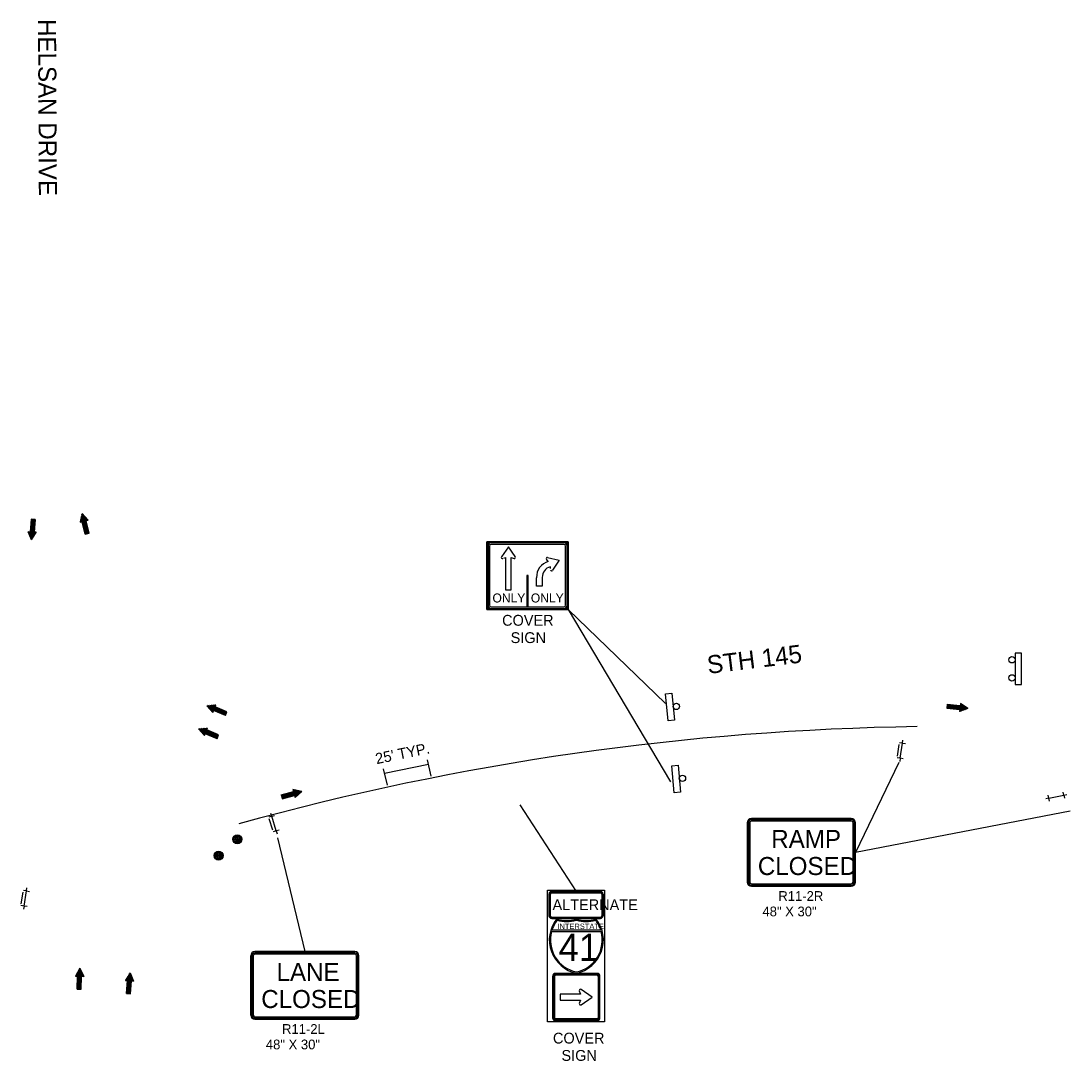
# Model space of a CAD drawing. Extents: x 358662 to 361839, y 132407 to 133741.
# Drawn here: x 360554 to 361135, y 133165 to 133741 of the extents above; entities that cross this region are included whole.
import ezdxf

# ---------------------------------------------------------------- set-up
doc = ezdxf.new("R2010")
doc.units = 0
for name, color, linetype in [('E_BLD_Dash', 7, 'Continuous'), ('E_BLD_Footing', 7, 'Continuous'), ('E_DTM_RandomShots', 7, 'Continuous'), ('E_MISCPROP_ShtDash', 7, 'Continuous'), ('E_WTR_Wetland', 7, 'Continuous'), ('P_FTMS_LaneLbl', 7, 'Continuous')]:
    doc.layers.add(name, color=color, linetype=linetype)

msp = doc.modelspace()

# ---------------------------------------------------------------- linework, layer by layer
at = {"layer": 'E_BLD_Dash'}
for p, q in [((361042.31, 133340.9), (361040.63, 133341.15)), ((361041.06, 133332.5), (361042.31, 133340.9)), ((361042.31, 133340.9), (361042.56, 133342.59)), ((361042.31, 133340.9), (361043.99, 133340.66)), ((361039.53, 133333.73), (361040.48, 133340.16)), ((361041.06, 133332.5), (361039.38, 133332.74)), ((361041.06, 133332.5), (361040.81, 133330.81)), ((361042.74, 133332.25), (361041.06, 133332.5)), ((361123.45, 133310.36), (361123.09, 133312.03)), ((361123.45, 133310.36), (361131.76, 133312.16)), ((361131.76, 133312.16), (361131.4, 133313.82)), ((361131.76, 133312.16), (361133.42, 133312.52)), ((361131.76, 133312.16), (361132.12, 133310.5)), ((361123.45, 133310.36), (361121.79, 133310.01)), ((361123.81, 133308.7), (361123.45, 133310.36)), ((360692.71, 133300.36), (360691.08, 133299.86)), ((360692.71, 133300.36), (360692.22, 133301.98)), ((360692.71, 133300.36), (360694.34, 133300.85)), ((360695.18, 133292.22), (360692.71, 133300.36)), ((360693.26, 133292.69), (360691.38, 133298.91)), ((360695.18, 133292.22), (360693.55, 133291.73)), ((360696.8, 133292.72), (360695.18, 133292.22)), ((360695.18, 133292.22), (360695.67, 133290.6)), ((360556.76, 133258.99), (360557.03, 133260.67)), ((360553.9, 133251.85), (360554.93, 133258.27)), ((360556.76, 133258.99), (360555.08, 133259.26)), ((360555.42, 133250.59), (360556.76, 133258.99)), ((360556.76, 133258.99), (360558.44, 133258.72)), ((360555.42, 133250.59), (360553.75, 133250.86)), ((360555.42, 133250.59), (360555.16, 133248.92)), ((360557.1, 133250.33), (360555.42, 133250.59))]:
    msp.add_line(p, q, dxfattribs=at)
for centre, radius in [((360673.65, 133287.65), 2.5), ((360673.65, 133287.65), 2), ((360673.65, 133287.65), 1.5), ((360673.65, 133287.65), 1), ((360673.65, 133287.65), 0.5), ((360673.65, 133287.65), 0.25), ((360663.24, 133278.55), 2.5), ((360663.24, 133278.55), 2), ((360663.24, 133278.55), 1.5), ((360663.24, 133278.55), 1), ((360663.24, 133278.55), 0.5), ((360663.24, 133278.55), 0.25)]:
    msp.add_circle(centre, radius, dxfattribs=at)
at = {"layer": 'E_BLD_Footing'}
for p, q in [((360559.31, 133465.13), (360558.79, 133458.03)), ((360559.76, 133465.1), (360559.01, 133454.97)), ((360561.56, 133464.96), (360559.31, 133465.13)), ((360560.21, 133465.06), (360559.4, 133454.07)), ((360560.66, 133465.03), (360559.84, 133453.92)), ((360561.11, 133465), (360560.35, 133454.78)), ((360560.43, 133465.05), (360560.43, 133465.05)), ((360561.56, 133464.96), (360561.03, 133457.86)), ((360587.58, 133468.18), (360586.54, 133463.38)), ((360586.54, 133463.38), (360590.9, 133464.5)), ((360586.75, 133463.45), (360586.65, 133463.86)), ((360587.19, 133463.57), (360586.86, 133464.84)), ((360587.62, 133463.68), (360587.07, 133465.82)), ((360589.85, 133456.87), (360587.28, 133466.79)), ((360590.28, 133456.98), (360587.49, 133467.77)), ((360587.58, 133468.18), (360590.9, 133464.5)), ((360589.41, 133456.76), (360587.63, 133463.65)), ((360590.72, 133457.1), (360587.96, 133467.77)), ((360591.16, 133457.21), (360588.61, 133467.04)), ((360589.8, 133464.24), (360589.26, 133466.32)), ((360591.59, 133457.32), (360589.81, 133464.22)), ((360590.24, 133464.36), (360589.92, 133465.59)), ((360590.67, 133464.47), (360590.57, 133464.87)), ((360562.15, 133457.77), (360557.67, 133458.11)), ((360559.62, 133453.56), (360557.67, 133458.11)), ((360557.89, 133458.07), (360557.86, 133457.66)), ((360558.34, 133458.03), (360558.24, 133456.76)), ((360558.79, 133458), (360558.63, 133455.86)), ((360559.62, 133453.56), (360562.15, 133457.77)), ((360561.03, 133457.83), (360560.87, 133455.63)), ((360561.48, 133457.8), (360561.38, 133456.49)), ((360561.93, 133457.77), (360561.9, 133457.35)), ((360589.41, 133456.76), (360591.59, 133457.32)), ((360590.5, 133457.04), (360590.5, 133457.04)), ((360656.83, 133361.66), (360661.76, 133362.08)), ((360656.83, 133361.66), (360660.03, 133357.93)), ((360667.39, 133357.05), (360657.11, 133361.34)), ((360667.56, 133357.47), (360657.39, 133361.71)), ((360667.21, 133356.63), (360657.76, 133360.58)), ((360667.73, 133357.88), (360658.36, 133361.79)), ((360660.44, 133358.97), (360658.41, 133359.82)), ((360660.27, 133358.56), (360659.06, 133359.06)), ((360661.31, 133361.05), (360659.33, 133361.87)), ((360660.1, 133358.14), (360659.71, 133358.3)), ((360660.03, 133357.93), (360661.76, 133362.08)), ((360661.48, 133361.46), (360660.31, 133361.96)), ((360667.04, 133356.22), (360660.47, 133358.96)), ((360661.66, 133361.88), (360661.28, 133362.04)), ((360667.91, 133358.3), (360661.33, 133361.04)), ((360667.04, 133356.22), (360667.91, 133358.3)), ((361067.18, 133362.55), (361066.92, 133360.31)), ((361066.92, 133360.31), (361074, 133359.5)), ((361066.97, 133360.76), (361077.06, 133359.6)), ((361067.03, 133361.21), (361077.97, 133359.94)), ((361067.05, 133361.43), (361067.05, 133361.43)), ((361067.08, 133361.65), (361078.14, 133360.38)), ((361067.13, 133362.1), (361077.31, 133360.93)), ((361067.18, 133362.55), (361074.25, 133361.73)), ((361074.39, 133362.85), (361073.87, 133358.38)), ((361078.5, 133360.14), (361073.87, 133358.38)), ((361073.92, 133358.6), (361074.33, 133358.55)), ((361073.97, 133359.05), (361075.24, 133358.9)), ((361074.02, 133359.49), (361076.15, 133359.25)), ((361074.28, 133361.73), (361076.47, 133361.48)), ((361074.33, 133362.18), (361075.64, 133362.03)), ((361074.38, 133362.62), (361074.8, 133362.57)), ((361078.5, 133360.14), (361074.39, 133362.85)), ((360667.47, 133357.26), (360667.47, 133357.26)), ((360652.21, 133348.82), (360657.14, 133349.24)), ((360652.21, 133348.82), (360655.41, 133345.09)), ((360662.76, 133344.21), (360652.48, 133348.5)), ((360662.94, 133344.63), (360652.77, 133348.87)), ((360662.59, 133343.8), (360653.13, 133347.74)), ((360663.11, 133345.04), (360653.74, 133348.95)), ((360655.82, 133346.13), (360653.78, 133346.98)), ((360656.69, 133348.21), (360654.71, 133349.04)), ((360655.41, 133345.09), (360657.14, 133349.24)), ((360656.86, 133348.63), (360655.68, 133349.12)), ((360657.03, 133349.04), (360656.65, 133349.2)), ((360663.28, 133345.46), (360656.71, 133348.2)), ((360655.65, 133345.72), (360654.43, 133346.22)), ((360655.47, 133345.3), (360655.08, 133345.47)), ((360662.42, 133343.38), (360655.84, 133346.12)), ((360662.42, 133343.38), (360663.28, 133345.46)), ((360662.85, 133344.42), (360662.85, 133344.42)), ((360697.92, 133312.25), (360704.8, 133314.1)), ((360697.92, 133312.25), (360698.51, 133310.08)), ((360698.04, 133311.82), (360707.93, 133314.48)), ((360698.16, 133311.38), (360708.91, 133314.28)), ((360698.27, 133310.95), (360708.91, 133313.81)), ((360698.39, 133310.51), (360708.19, 133313.15)), ((360698.51, 133310.08), (360705.38, 133311.93)), ((360709.33, 133314.19), (360704.51, 133315.19)), ((360704.51, 133315.19), (360705.68, 133310.84)), ((360704.59, 133314.98), (360705, 133315.09)), ((360704.71, 133314.54), (360705.98, 133314.89)), ((360704.82, 133314.11), (360706.96, 133314.68)), ((360705.41, 133311.94), (360707.48, 133312.49)), ((360705.53, 133311.5), (360706.76, 133311.83)), ((360709.33, 133314.19), (360705.68, 133310.84)), ((360698.21, 133311.17), (360698.21, 133311.17)), ((360705.64, 133311.07), (360706.04, 133311.17)), ((360586.41, 133216.1), (360584, 133211.81)), ((360584.68, 133211.8), (360584.74, 133213.11)), ((360585.13, 133211.78), (360585.23, 133213.98)), ((360585.25, 133204.62), (360585.72, 133214.86)), ((360585.7, 133204.6), (360586.21, 133215.73)), ((360586.15, 133204.58), (360586.65, 133215.59)), ((360586.41, 133216.1), (360588.5, 133211.6)), ((360586.6, 133204.56), (360587.06, 133214.7)), ((360587.37, 133211.68), (360587.47, 133213.82)), ((360587.82, 133211.66), (360587.88, 133212.93)), ((360614.19, 133213.62), (360611.65, 133209.4)), ((360613.14, 133202.15), (360613.97, 133213.25)), ((360613.59, 133202.11), (360614.41, 133213.1)), ((360614.19, 133213.62), (360616.14, 133209.07)), ((360584, 133211.81), (360588.5, 133211.6)), ((360584.23, 133211.82), (360584.25, 133212.24)), ((360584.8, 133204.64), (360585.13, 133211.75)), ((360587.05, 133204.54), (360587.37, 133211.65)), ((360588.27, 133211.64), (360588.29, 133212.05)), ((360611.65, 133209.4), (360616.14, 133209.07)), ((360611.88, 133209.41), (360611.91, 133209.83)), ((360612.24, 133202.21), (360612.78, 133209.31)), ((360612.33, 133209.38), (360612.43, 133210.69)), ((360612.69, 133202.18), (360613.46, 133212.4)), ((360612.78, 133209.34), (360612.94, 133211.54)), ((360614.04, 133202.08), (360614.8, 133212.2)), ((360614.49, 133202.05), (360615.02, 133209.15)), ((360615.02, 133209.17), (360615.18, 133211.31)), ((360615.47, 133209.14), (360615.57, 133210.41)), ((360615.92, 133209.11), (360615.95, 133209.52)), ((360584.8, 133204.64), (360587.05, 133204.54)), ((360585.93, 133204.59), (360585.93, 133204.59)), ((360612.24, 133202.21), (360614.49, 133202.05)), ((360613.37, 133202.13), (360613.37, 133202.13))]:
    msp.add_line(p, q, dxfattribs=at)
at = {"layer": 'E_DTM_RandomShots'}
msp.add_arc((361071.64, 131864.2), 1486, 90.81641, 105.50174, dxfattribs=at)
at = {"layer": 'E_MISCPROP_ShtDash'}
for p, q in [((360956.29, 133296.73), (360956.29, 133263.9)), ((360956.92, 133296.73), (360956.92, 133263.9)), ((360957.7, 133296.71), (360957.7, 133263.9)), ((361013.97, 133299.07), (360958.64, 133299.07)), ((361013.97, 133298.45), (360958.64, 133298.45)), ((361013.97, 133297.66), (360958.64, 133297.66)), ((361014.91, 133263.9), (361014.91, 133296.73)), ((361015.69, 133263.9), (361015.69, 133296.73)), ((361016.31, 133263.9), (361016.31, 133296.73)), ((360958.64, 133262.96), (361013.97, 133262.96)), ((360958.64, 133262.18), (361013.97, 133262.18)), ((360958.64, 133261.56), (361013.97, 133261.56)), ((360738.73, 133225.35), (360683.4, 133225.35)), ((360738.73, 133224.73), (360683.4, 133224.73)), ((360681.05, 133223.01), (360681.05, 133190.19)), ((360681.68, 133223.01), (360681.68, 133190.19)), ((360682.46, 133222.99), (360682.46, 133190.19)), ((360738.73, 133223.95), (360683.4, 133223.95)), ((360739.67, 133190.19), (360739.67, 133223.01)), ((360740.45, 133190.19), (360740.45, 133223.01)), ((360741.07, 133190.19), (360741.07, 133223.01)), ((360683.4, 133189.25), (360738.73, 133189.25)), ((360683.4, 133188.47), (360738.73, 133188.47)), ((360683.4, 133187.84), (360738.73, 133187.84))]:
    msp.add_line(p, q, dxfattribs=at)
for centre, radius, start, end in [((360958.64, 133296.73), 2.34, 90, 180), ((360958.64, 133296.73), 1.72, 90, 180), ((360958.64, 133296.73), 0.938, 90, 181.0779), ((361013.97, 133296.73), 2.34, 0, 90), ((361013.97, 133296.73), 1.72, 0, 90), ((361013.97, 133296.73), 0.938, 0, 90), ((360958.64, 133263.9), 2.34, 180, 270), ((360958.64, 133263.9), 1.72, 180, 270), ((360958.64, 133263.9), 0.938, 180, 270), ((361013.97, 133263.9), 0.938, 270, 360), ((361013.97, 133263.9), 1.72, 270, 360), ((361013.97, 133263.9), 2.34, 270, 360), ((360683.4, 133223.01), 2.34, 90, 180), ((360683.4, 133223.01), 1.72, 90, 180), ((360738.73, 133223.01), 2.34, 0, 90), ((360738.73, 133223.01), 1.72, 0, 90), ((360683.4, 133223.01), 0.938, 90, 181.0779), ((360738.73, 133223.01), 0.938, 0, 90), ((360683.4, 133190.19), 2.34, 180, 270), ((360683.4, 133190.19), 1.72, 180, 270), ((360683.4, 133190.19), 0.938, 180, 270), ((360738.73, 133190.19), 0.938, 270, 360), ((360738.73, 133190.19), 1.72, 270, 360), ((360738.73, 133190.19), 2.34, 270, 360)]:
    msp.add_arc(centre, radius, start, end, dxfattribs=at)
at = {"layer": 'E_WTR_Wetland'}
for p, q in [((360812.01, 133452.48), (360812.01, 133449.65)), ((360857.01, 133452.48), (360812.01, 133452.48)), ((360854.67, 133451.86), (360814.36, 133451.86)), ((360857.01, 133414.98), (360857.01, 133452.48)), ((360812.01, 133449.65), (360812.01, 133414.98)), ((360813.42, 133450.14), (360813.42, 133417.33)), ((360854.67, 133451.08), (360814.36, 133451.08)), ((360823.91, 133449.72), (360820.08, 133444.25)), ((360827.71, 133444.29), (360823.91, 133449.72)), ((360855.61, 133417.33), (360855.61, 133450.14)), ((360821.44, 133443.5), (360822.35, 133443.78)), ((360822.35, 133443.78), (360822.35, 133439.41)), ((360825.48, 133440.06), (360825.48, 133443.78)), ((360825.48, 133443.78), (360827.02, 133443.33)), ((360825.48, 133425.82), (360825.48, 133440.06)), ((360846.01, 133441.51), (360844.98, 133442.82)), ((360845.61, 133443.82), (360852.06, 133442.33)), ((360852.06, 133442.33), (360848.43, 133436.73)), ((360822.35, 133439.48), (360822.35, 133425.82)), ((360847.23, 133437.7), (360847.15, 133438.57)), ((360839.56, 133427.92), (360839.56, 133432.61)), ((360842.69, 133427.92), (360839.56, 133427.92)), ((360842.69, 133432.76), (360842.69, 133427.92)), ((360812.01, 133425.84), (360812.01, 133423.89)), ((360822.35, 133425.82), (360825.48, 133425.82)), ((360814.36, 133416.39), (360834.12, 133416.39)), ((360834.12, 133416.39), (360834.9, 133416.39)), ((360812.01, 133414.98), (360857.01, 133414.98)), ((360846.39, 133257.27), (360846.39, 133245.27)), ((360846.77, 133257.27), (360846.77, 133245.27)), ((360847.14, 133257.27), (360847.14, 133245.27)), ((360847.89, 133258.77), (360874.89, 133258.77)), ((360847.89, 133258.4), (360874.89, 133258.4)), ((360847.89, 133258.02), (360874.89, 133258.02)), ((360875.64, 133257.27), (360875.64, 133245.27)), ((360876.02, 133257.27), (360876.02, 133245.27)), ((360876.39, 133257.27), (360876.39, 133245.27)), ((360847.89, 133244.52), (360874.89, 133244.52)), ((360847.89, 133244.15), (360874.89, 133244.15)), ((360847.89, 133243.77), (360874.89, 133243.77)), ((360847.83, 133236.55), (360875.32, 133236.55)), ((360875.13, 133237.18), (360848.02, 133237.18)), ((360873.02, 133213.28), (360850.06, 133213.28)), ((360873.02, 133212.85), (360850.06, 133212.85)), ((360848.42, 133211.64), (360848.42, 133188.67)), ((360848.85, 133211.64), (360848.85, 133188.67)), ((360849.4, 133211.64), (360849.4, 133188.67)), ((360873.02, 133212.3), (360850.06, 133212.3)), ((360873.68, 133211.64), (360873.68, 133188.67)), ((360874.23, 133211.64), (360874.23, 133188.67)), ((360874.67, 133188.67), (360874.67, 133211.64)), ((360863.78, 133201.8), (360852.57, 133201.8)), ((360852.57, 133201.8), (360852.57, 133198.52)), ((360863.21, 133203.69), (360863.78, 133201.8)), ((360870.4, 133200.16), (360864.21, 133204.42)), ((360852.57, 133198.52), (360863.78, 133198.52)), ((360863.78, 133198.52), (360863.21, 133196.63)), ((360864.21, 133195.9), (360870.4, 133200.16)), ((360873.02, 133188.02), (360850.06, 133188.02)), ((360873.02, 133187.47), (360850.06, 133187.47)), ((360850.06, 133187.03), (360873.02, 133187.03))]:
    msp.add_line(p, q, dxfattribs=at)
for points in [[(360812.64, 133450.14), (360812.64, 133417.33)], [(360856.39, 133417.33), (360856.39, 133450.14)], [(360834.9, 133416.39), (360834.9, 133433.89), (360834.12, 133433.89), (360834.12, 133416.39)], [(360834.12, 133416.39), (360834.9, 133416.39)], [(360834.9, 133416.39), (360854.67, 133416.39)], [(360814.36, 133415.61), (360854.67, 133415.61)]]:
    msp.add_lwpolyline(points, dxfattribs=at)
for points in [[(361104.73, 133373.35), (361108.23, 133373.35), (361108.23, 133390.85), (361104.73, 133390.85)], [(360915.96, 133353.63), (360912.48, 133353.3), (360911.05, 133368.23), (360914.54, 133368.56)], [(360919.36, 133313.8), (360915.87, 133313.46), (360914.45, 133328.4), (360917.93, 133328.73)]]:
    msp.add_lwpolyline(points, close=True, dxfattribs=at)
for centre in [(361102.98, 133387.1), (361102.98, 133377.1), (360916.99, 133361.26), (360920.39, 133321.43)]:
    msp.add_circle(centre, 1.75, dxfattribs=at)
for centre, radius, start, end in [((360814.36, 133450.14), 2.34, 90, 180), ((360814.36, 133450.14), 1.72, 90, 180), ((360854.67, 133450.14), 2.34, 0, 90), ((360854.67, 133450.14), 1.72, 360, 90), ((360814.36, 133450.14), 0.938, 90, 180), ((360854.67, 133450.14), 0.938, 360, 90), ((360820.6, 133443.89), 0.625, 145.00068, 287.11601), ((360827.2, 133443.93), 0.625, 253.83728, 34.99884), ((360848.3, 133433.07), 8.75, 105.18604, 182.91906), ((360845.47, 133443.21), 0.625, 76.99486, 218.15642), ((360848.3, 133433.07), 5.63, 101.82178, 182.91906), ((360847.91, 133437.07), 0.625, 184.87769, 326.99302), ((360814.36, 133417.33), 2.34, 180, 270), ((360814.36, 133417.33), 1.72, 180, 270), ((360814.36, 133417.33), 0.938, 180, 270), ((360854.67, 133417.33), 1.72, 270, 360), ((360854.67, 133417.33), 0.938, 270, 360), ((360854.67, 133417.33), 2.34, 270, 0), ((360847.89, 133257.27), 1.5, 90, 180), ((360847.89, 133257.27), 1.13, 90, 180), ((360847.89, 133257.27), 0.75, 90, 180), ((360874.89, 133257.27), 1.5, 0, 90), ((360874.89, 133257.27), 1.13, 0, 90), ((360874.89, 133257.27), 0.75, 0, 90), ((360847.89, 133245.27), 1.5, 180, 270), ((360865.32, 133231.8), 18.75, 141.66896, 258.46304), ((360847.89, 133245.27), 1.13, 180, 270), ((360847.89, 133245.27), 0.75, 180, 270), ((360865.32, 133231.8), 18.12, 143.00407, 162.74499), ((360856.1, 133261.36), 18.75, 253.00398, 286.99096), ((360856.1, 133261.36), 19.37, 254.28765, 286.42705), ((360857.82, 133231.8), 18.75, 281.53696, 38.33104), ((360867.05, 133261.36), 18.75, 253.00904, 286.99602), ((360867.05, 133261.36), 19.37, 253.57295, 285.71235), ((360857.82, 133231.8), 18.12, 17.25501, 36.99593), ((360874.89, 133245.27), 1.5, 270, 360), ((360874.89, 133245.27), 1.13, 270, 360), ((360874.89, 133245.27), 0.75, 270, 360), ((360865.32, 133231.8), 18.12, 164.80279, 258.05946), ((360857.82, 133231.8), 18.12, 281.94054, 15.19721), ((360850.06, 133211.64), 1.64, 90, 180), ((360850.06, 133211.64), 1.2, 90, 180), ((360873.02, 133211.64), 1.64, 0, 90), ((360873.02, 133211.64), 1.2, 0, 90), ((360850.06, 133211.64), 0.656, 90, 180), ((360873.02, 133211.64), 0.656, 0, 90), ((360863.84, 133203.88), 0.656, 55.47033, 196.8026), ((360863.84, 133196.44), 0.656, 163.1974, 304.52967), ((360850.06, 133188.67), 1.64, 180, 270), ((360850.06, 133188.67), 1.2, 180, 270), ((360850.06, 133188.67), 0.656, 180, 270), ((360873.02, 133188.67), 1.64, 270, 0), ((360873.02, 133188.67), 0.656, 270, 0), ((360873.02, 133188.67), 1.2, 270, 0), ((360873.02, 133188.67), 1.64, 330.60346, 0)]:
    msp.add_arc(centre, radius, start, end, dxfattribs=at)
at = {"layer": 'P_FTMS_LaneLbl'}
for p, q in [((360857.01, 133414.98), (360910.94, 133362.91)), ((360857.01, 133414.98), (360913.75, 133319.43)), ((360755.27, 133324.31), (360779.57, 133329.35)), ((360781.18, 133322.6), (360779.01, 133331.73)), ((361040.24, 133330.26), (361016.31, 133280.31)), ((360756.87, 133317.6), (360754.7, 133326.73)), ((360830.18, 133306.63), (360861.39, 133258.77)), ((361135.18, 133303.13), (361016.31, 133280.31)), ((360695.97, 133288.38), (360711.06, 133225.35))]:
    msp.add_line(p, q, dxfattribs=at)
for points in [[(360812.01, 133452.48), (360857.01, 133452.48), (360857.01, 133414.98), (360812.01, 133414.98)], [(360845.54, 133259.35), (360877.15, 133259.35), (360877.15, 133186.37), (360845.54, 133186.37)]]:
    msp.add_lwpolyline(points, close=True, dxfattribs=at)

# ---------------------------------------------------------------- texts
at = {"layer": 'E_MISCPROP_ShtDash'}
for s, height, p in [('RAMP', 10, (360969.59, 133282.82)), ('CLOSED', 10, (360962.15, 133267.81)), ('R11-2R', 5.4, (360973.53, 133253.49)), ('48" X 30"', 5.4, (360964.71, 133244.92)), ('LANE', 10, (360695.41, 133209.1)), ('CLOSED', 10, (360686.91, 133194.09)), ('R11-2L', 5.4, (360698.45, 133179.77)), ('48" X 30"', 5.4, (360689.47, 133171.2))]:
    msp.add_text(s, height=height, dxfattribs=at).set_placement(p)
at = {"layer": 'E_WTR_Wetland'}
for s, height, p in [('ONLY', 5, (360815.07, 133418.87)), ('ONLY', 5, (360836.34, 133418.87)), ('ALTERNATE', 6, (360848.36, 133248.34)), ('INTERSTATE', 3, (360851.07, 133237.88)), ('41', 15, (360851.75, 133220.23))]:
    msp.add_text(s, height=height, dxfattribs=at).set_placement(p)
at = {"layer": 'P_FTMS_LaneLbl'}
for s, height, rotation, p in [('HELSAN DRIVE', 10, 270.28062, (360563.18, 133742.23)), ('STH 145', 10, 6.94981, (360934.66, 133379.28)), ("25' TYP.", 6, 11.58237, (360750.86, 133329.23))]:
    msp.add_text(s, height=height, rotation=rotation, dxfattribs=at).set_placement(p)
for s, p in [('COVER', (360820.42, 133405.99)), ('SIGN', (360825.15, 133396.39)), ('COVER', (360848.6, 133174.41)), ('SIGN', (360853.32, 133164.81))]:
    msp.add_text(s, height=6, dxfattribs=at).set_placement(p)

doc.saveas('drawing.dxf')
